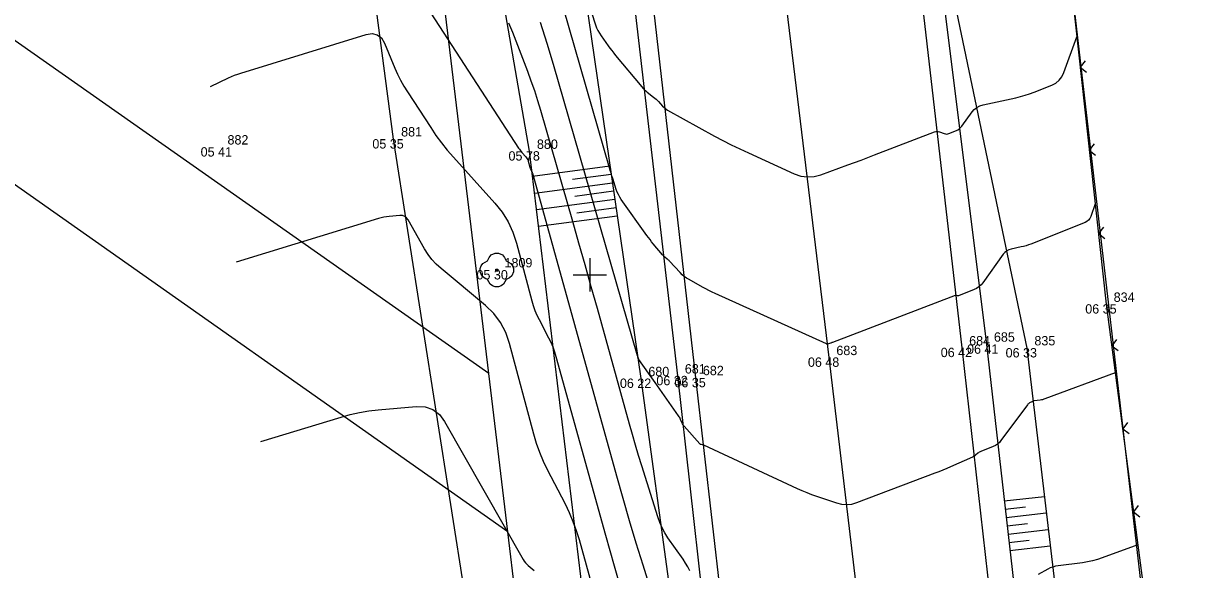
# Model space of a CAD drawing. Extents: x -711234 to -710007, y -1026313 to -1025448.
# Drawn here: x -710916.93 to -710881.89, y -1026008.8 to -1025992.49 of the extents above; entities that cross this region are included whole.
import ezdxf

# ---------------------------------------------------------------- set-up
doc = ezdxf.new("R2010")
doc.units = 0
for name, color, linetype in [('Ex_Major Contours', 7, 'Continuous'), ('Ex_Minor Contours', 7, 'Continuous'), ('Z_body', 7, 'Continuous'), ('Z_body_cisla', 7, 'Continuous'), ('Z_body_vysky_redukovane', 7, 'Continuous'), ('Z_hektometricka_sit', 7, 'Continuous'), ('Z_hrany_paty', 7, 'Continuous'), ('Z_katastr_hranice', 7, 'Continuous'), ('Z_komunikace', 7, 'Continuous'), ('Z_komunikace_osa', 7, 'Continuous'), ('Z_ploty', 7, 'Continuous'), ('Z_ploty_znacky', 7, 'Continuous'), ('Z_pole_rozhranni', 7, 'Continuous'), ('Z_technicke_srafy', 7, 'Continuous'), ('Z_vdz12_plna', 7, 'Continuous'), ('Z_zelen_jednotliva', 7, 'Continuous')]:
    doc.layers.add(name, color=color, linetype=linetype)

# ---------------------------------------------------------------- blocks, each defined once
blk = doc.blocks.new('POINT_DISPLAY')
blk.add_line((0, 0), (0, 0))
blk = doc.blocks.new('Z24')
for p, q in [((-0.28, 0.28), (-0.23, 0.38)), ((-0.23, 0.38), (-0.17, 0.45)), ((-0.17, 0.45), (-0.05, 0.5)), ((-0.05, 0.5), (0.05, 0.5)), ((0.05, 0.5), (0.17, 0.45)), ((0.17, 0.45), (0.23, 0.38)), ((0.23, 0.38), (0.28, 0.28)), ((-0.5, 0.05), (-0.47, 0.13)), ((-0.5, -0.05), (-0.5, 0.05)), ((-0.47, 0.13), (-0.42, 0.2)), ((-0.42, 0.2), (-0.28, 0.28)), ((-0.03, -0.03), (-0.03, 0.03)), ((-0.03, 0.03), (0.03, 0.03)), ((0.03, 0.03), (0.03, -0.03)), ((0.28, 0.28), (0.42, 0.2)), ((0.42, 0.2), (0.47, 0.13)), ((0.47, 0.13), (0.5, 0.05)), ((0.5, 0.05), (0.5, -0.05)), ((-0.45, -0.17), (-0.5, -0.05)), ((-0.38, -0.23), (-0.45, -0.17)), ((-0.28, -0.28), (-0.38, -0.23)), ((-0.2, -0.42), (-0.28, -0.28)), ((0.03, -0.03), (-0.03, -0.03)), ((0.28, -0.28), (0.2, -0.42)), ((0.38, -0.23), (0.28, -0.28)), ((0.45, -0.17), (0.38, -0.23)), ((0.5, -0.05), (0.45, -0.17)), ((-0.13, -0.47), (-0.2, -0.42)), ((-0.05, -0.5), (-0.13, -0.47)), ((0.05, -0.5), (-0.05, -0.5)), ((0.13, -0.47), (0.05, -0.5)), ((0.2, -0.42), (0.13, -0.47))]:
    blk.add_line(p, q)
blk = doc.blocks.new('Z212')
for p, q in [((-0.17, 0.17), (0, 0)), ((0, 0), (0.17, 0.17))]:
    blk.add_line(p, q)

msp = doc.modelspace()

# ---------------------------------------------------------------- linework, layer by layer
at = {"layer": 'Ex_Major Contours'}
for points in [[(-710897.009, -1026008.843), (-710897.072, -1026008.725), (-710897.14, -1026008.61), (-710897.214, -1026008.499), (-710897.664, -1026007.856), (-710897.758, -1026007.709), (-710897.841, -1026007.556), (-710897.911, -1026007.397), (-710897.97, -1026007.233), (-710898.446, -1026005.707), (-710898.541, -1026005.396), (-710898.635, -1026005.085), (-710898.725, -1026004.773), (-710898.813, -1026004.46), (-710899.773, -1026001.009), (-710899.955, -1026000.357), (-710900.138, -1025999.706), (-710900.323, -1025999.055), (-710900.51, -1025998.405), (-710901.463, -1025995.099), (-710901.552, -1025994.803), (-710901.647, -1025994.508), (-710901.749, -1025994.216), (-710901.856, -1025993.926), (-710902.299, -1025992.769), (-710902.417, -1025992.484)], [(-710909.834, -1026004.985), (-710907.436, -1026004.253), (-710907.162, -1026004.177), (-710906.885, -1026004.116), (-710906.606, -1026004.069), (-710906.324, -1026004.037), (-710905.188, -1026003.939), (-710904.922, -1026003.949), (-710904.692, -1026004.026), (-710904.497, -1026004.172), (-710904.339, -1026004.385), (-710901.991, -1026008.509), (-710901.96, -1026008.559), (-710901.924, -1026008.605), (-710901.885, -1026008.647), (-710901.842, -1026008.686), (-710901.662, -1026008.836)], [(-710883.621, -1026008.064), (-710884.686, -1026008.458), (-710884.828, -1026008.506), (-710884.973, -1026008.546), (-710885.12, -1026008.577), (-710885.268, -1026008.6), (-710886.003, -1026008.693), (-710886.083, -1026008.707), (-710886.161, -1026008.729), (-710886.236, -1026008.758), (-710886.308, -1026008.795), (-710886.594, -1026008.957)]]:
    msp.add_lwpolyline(points, dxfattribs=at)
at = {"layer": 'Ex_Minor Contours'}
for points in [[(-710884.89, -1025997.884), (-710885.027, -1025998.261), (-710885.055, -1025998.319), (-710885.092, -1025998.367), (-710885.139, -1025998.406), (-710885.197, -1025998.436), (-710886.817, -1025999.083), (-710886.888, -1025999.11), (-710886.96, -1025999.133), (-710887.033, -1025999.154), (-710887.107, -1025999.171), (-710887.403, -1025999.235), (-710887.474, -1025999.257), (-710887.537, -1025999.29), (-710887.592, -1025999.334), (-710887.64, -1025999.39), (-710888.252, -1026000.239), (-710888.306, -1026000.304), (-710888.368, -1026000.36), (-710888.436, -1026000.406), (-710888.512, -1026000.443), (-710888.974, -1026000.629), (-710888.982, -1026000.632), (-710888.991, -1026000.633), (-710888.999, -1026000.632), (-710889.008, -1026000.63), (-710889.043, -1026000.617), (-710889.051, -1026000.615), (-710889.06, -1026000.614), (-710889.069, -1026000.615), (-710889.077, -1026000.618), (-710892.749, -1026002.022), (-710892.764, -1026002.028), (-710892.779, -1026002.033), (-710892.794, -1026002.039), (-710892.809, -1026002.044), (-710892.868, -1026002.066), (-710892.883, -1026002.07), (-710892.898, -1026002.071), (-710892.912, -1026002.069), (-710892.927, -1026002.064), (-710896.248, -1026000.561), (-710896.344, -1026000.516), (-710896.439, -1026000.47), (-710896.534, -1026000.421), (-710896.627, -1026000.371), (-710897.034, -1026000.146), (-710897.107, -1026000.102), (-710897.175, -1026000.053), (-710897.239, -1025999.998), (-710897.299, -1025999.937), (-710897.614, -1025999.594), (-710897.631, -1025999.577), (-710897.648, -1025999.561), (-710897.666, -1025999.545), (-710897.684, -1025999.53), (-710897.759, -1025999.471), (-710897.777, -1025999.456), (-710897.795, -1025999.44), (-710897.812, -1025999.423), (-710897.827, -1025999.406), (-710898.101, -1025999.076), (-710898.151, -1025999.015), (-710898.2, -1025998.952), (-710898.248, -1025998.889), (-710898.295, -1025998.825), (-710899.059, -1025997.749), (-710899.105, -1025997.679), (-710899.145, -1025997.606), (-710899.18, -1025997.53), (-710899.209, -1025997.451), (-710899.313, -1025997.13), (-710899.339, -1025997.05), (-710899.364, -1025996.969), (-710899.388, -1025996.888), (-710899.412, -1025996.807), (-710900.786, -1025992.042)], [(-710900.066, -1025991.799), (-710899.826, -1025992.536), (-710899.795, -1025992.622), (-710899.757, -1025992.704), (-710899.714, -1025992.784), (-710899.664, -1025992.86), (-710899.452, -1025993.158), (-710899.398, -1025993.232), (-710899.343, -1025993.305), (-710899.286, -1025993.377), (-710899.229, -1025993.448), (-710898.448, -1025994.386), (-710898.411, -1025994.428), (-710898.371, -1025994.469), (-710898.33, -1025994.507), (-710898.286, -1025994.543), (-710898.092, -1025994.694), (-710898.055, -1025994.724), (-710898.019, -1025994.755), (-710897.985, -1025994.789), (-710897.951, -1025994.823), (-710897.822, -1025994.965), (-710897.788, -1025994.999), (-710897.752, -1025995.029), (-710897.713, -1025995.057), (-710897.673, -1025995.082), (-710896.272, -1025995.856), (-710896.023, -1025995.99), (-710895.771, -1025996.119), (-710895.518, -1025996.243), (-710895.261, -1025996.363), (-710893.889, -1025996.983), (-710893.693, -1025997.052), (-710893.496, -1025997.079), (-710893.297, -1025997.067), (-710893.096, -1025997.014), (-710892.291, -1025996.721), (-710892.09, -1025996.648), (-710891.889, -1025996.573), (-710891.689, -1025996.498), (-710891.489, -1025996.422), (-710889.693, -1025995.735), (-710889.658, -1025995.725), (-710889.622, -1025995.722), (-710889.587, -1025995.724), (-710889.551, -1025995.734), (-710889.408, -1025995.785), (-710889.372, -1025995.794), (-710889.337, -1025995.797), (-710889.301, -1025995.793), (-710889.266, -1025995.782), (-710889.042, -1025995.692), (-710888.995, -1025995.669), (-710888.953, -1025995.641), (-710888.915, -1025995.606), (-710888.882, -1025995.566), (-710888.574, -1025995.139), (-710888.507, -1025995.061), (-710888.43, -1025995), (-710888.343, -1025994.954), (-710888.245, -1025994.924), (-710887.264, -1025994.713), (-710887.126, -1025994.68), (-710886.989, -1025994.641), (-710886.854, -1025994.597), (-710886.721, -1025994.547), (-710886.191, -1025994.336), (-710886.069, -1025994.273), (-710885.969, -1025994.189), (-710885.889, -1025994.086), (-710885.83, -1025993.962), (-710885.441, -1025992.89)], [(-710904.75, -1025992.192), (-710902.129, -1025996.215), (-710902.106, -1025996.25), (-710902.081, -1025996.283), (-710902.055, -1025996.315), (-710902.028, -1025996.347), (-710901.911, -1025996.477), (-710901.888, -1025996.505), (-710901.869, -1025996.536), (-710901.854, -1025996.569), (-710901.842, -1025996.604), (-710901.793, -1025996.789), (-710901.788, -1025996.804), (-710901.783, -1025996.819), (-710901.777, -1025996.834), (-710901.769, -1025996.849), (-710901.739, -1025996.907), (-710901.732, -1025996.921), (-710901.726, -1025996.936), (-710901.721, -1025996.952), (-710901.716, -1025996.967), (-710899.204, -1026006.006), (-710899.015, -1026006.674), (-710898.822, -1026007.341), (-710898.623, -1026008.006), (-710898.418, -1026008.669), (-710897.225, -1026012.492)], [(-710884.292, -1026002.933), (-710886.394, -1026003.71), (-710886.428, -1026003.721), (-710886.463, -1026003.731), (-710886.499, -1026003.738), (-710886.535, -1026003.744), (-710886.713, -1026003.767), (-710886.732, -1026003.77), (-710886.751, -1026003.775), (-710886.769, -1026003.782), (-710886.787, -1026003.791), (-710886.856, -1026003.83), (-710886.873, -1026003.841), (-710886.888, -1026003.853), (-710886.902, -1026003.867), (-710886.914, -1026003.882), (-710887.709, -1026004.953), (-710887.757, -1026005.009), (-710887.811, -1026005.057), (-710887.872, -1026005.098), (-710887.939, -1026005.13), (-710888.313, -1026005.279), (-710888.335, -1026005.289), (-710888.357, -1026005.301), (-710888.378, -1026005.314), (-710888.397, -1026005.329), (-710888.474, -1026005.392), (-710888.494, -1026005.407), (-710888.515, -1026005.421), (-710888.536, -1026005.433), (-710888.558, -1026005.444), (-710889.214, -1026005.734), (-710889.331, -1026005.785), (-710889.449, -1026005.834), (-710889.567, -1026005.882), (-710889.686, -1026005.928), (-710892.028, -1026006.816), (-710892.175, -1026006.858), (-710892.323, -1026006.874), (-710892.47, -1026006.863), (-710892.619, -1026006.826), (-710893.213, -1026006.625), (-710893.36, -1026006.572), (-710893.506, -1026006.516), (-710893.651, -1026006.456), (-710893.794, -1026006.392), (-710896.591, -1026005.092), (-710896.601, -1026005.088), (-710896.61, -1026005.084), (-710896.62, -1026005.082), (-710896.631, -1026005.08), (-710896.672, -1026005.073), (-710896.682, -1026005.071), (-710896.691, -1026005.067), (-710896.699, -1026005.061), (-710896.707, -1026005.054), (-710897.177, -1026004.526), (-710897.196, -1026004.503), (-710897.212, -1026004.479), (-710897.227, -1026004.454), (-710897.239, -1026004.428), (-710897.286, -1026004.32), (-710897.299, -1026004.294), (-710897.313, -1026004.268), (-710897.327, -1026004.243), (-710897.344, -1026004.218), (-710898.044, -1026003.218), (-710898.093, -1026003.147), (-710898.143, -1026003.076), (-710898.193, -1026003.006), (-710898.243, -1026002.935), (-710898.533, -1026002.527), (-710898.538, -1026002.519), (-710898.542, -1026002.511), (-710898.546, -1026002.503), (-710898.549, -1026002.495), (-710898.56, -1026002.46), (-710898.566, -1026002.443), (-710898.571, -1026002.426), (-710901.081, -1025993.723), (-710901.271, -1025993.09), (-710901.474, -1025992.461)], [(-710911.343, -1025994.376), (-710910.802, -1025994.121), (-710910.711, -1025994.08), (-710910.619, -1025994.042), (-710910.526, -1025994.008), (-710910.431, -1025993.977), (-710906.682, -1025992.827), (-710906.503, -1025992.798), (-710906.353, -1025992.831), (-710906.231, -1025992.926), (-710906.139, -1025993.082), (-710905.827, -1025993.828), (-710905.745, -1025994.013), (-710905.655, -1025994.193), (-710905.556, -1025994.369), (-710905.45, -1025994.541), (-710904.755, -1025995.607), (-710904.598, -1025995.838), (-710904.433, -1025996.062), (-710904.259, -1025996.28), (-710904.076, -1025996.491), (-710902.838, -1025997.864), (-710902.623, -1025998.132), (-710902.443, -1025998.42), (-710902.3, -1025998.727), (-710902.192, -1025999.053), (-710901.733, -1026000.776), (-710901.69, -1026000.922), (-710901.64, -1026001.064), (-710901.581, -1026001.204), (-710901.515, -1026001.34), (-710901.235, -1026001.88), (-710901.169, -1026002.016), (-710901.11, -1026002.156), (-710901.058, -1026002.298), (-710901.014, -1026002.443), (-710899.53, -1026007.782), (-710899.274, -1026008.69), (-710899.01, -1026009.597)], [(-710899.522, -1026010.761), (-710900.312, -1026007.919), (-710900.396, -1026007.644), (-710900.494, -1026007.375), (-710900.606, -1026007.111), (-710900.731, -1026006.853), (-710901.261, -1026005.831), (-710901.386, -1026005.573), (-710901.496, -1026005.309), (-710901.592, -1026005.039), (-710901.674, -1026004.764), (-710902.397, -1026002.049), (-710902.51, -1026001.723), (-710902.669, -1026001.426), (-710902.872, -1026001.158), (-710903.12, -1026000.918), (-710904.447, -1025999.816), (-710904.589, -1025999.686), (-710904.718, -1025999.545), (-710904.834, -1025999.393), (-710904.937, -1025999.23), (-710905.432, -1025998.36), (-710905.478, -1025998.299), (-710905.533, -1025998.257), (-710905.599, -1025998.235), (-710905.675, -1025998.233), (-710906, -1025998.261), (-710906.08, -1025998.27), (-710906.16, -1025998.283), (-710906.239, -1025998.301), (-710906.317, -1025998.322), (-710910.575, -1025999.622)]]:
    msp.add_lwpolyline(points, dxfattribs=at)
at = {"layer": 'Z_hektometricka_sit'}
for p, q in [((-710900, -1025999.5), (-710900, -1026000.5)), ((-710900.5, -1026000), (-710899.5, -1026000))]:
    msp.add_line(p, q, dxfattribs=at)
at = {"layer": 'Z_hrany_paty'}
for p, q in [((-710901.8, -1025996.31), (-710904.29, -1025982.08)), ((-710900.9, -1025986.46), (-710898.47, -1026003.1)), ((-710889.89, -1025988.09), (-710886.94, -1026002.19)), ((-710899.51, -1026015.29), (-710901.8, -1025996.31)), ((-710886.94, -1026002.19), (-710885.11, -1026017.61)), ((-710898.47, -1026003.1), (-710896.6, -1026016.91))]:
    msp.add_line(p, q, dxfattribs=at)
at = {"layer": 'Z_katastr_hranice'}
for p, q in [((-710902.45, -1026007.68), (-710961.26, -1025966.3)), ((-710902.45, -1026007.68), (-710903.02, -1026002.95)), ((-710896.69, -1026055.45), (-710902.45, -1026007.68))]:
    msp.add_line(p, q, dxfattribs=at)
for points in [[(-710903.02, -1026002.95), (-710907.6, -1025964.93), (-710910.15, -1025942.26)], [(-710903.02, -1026002.95), (-710959.27, -1025963.47), (-710961.26, -1025966.3)], [(-710869.22, -1026132.07), (-710876.56, -1026069.18), (-710887.07, -1025978.66), (-710888.56, -1025976.86)]]:
    msp.add_lwpolyline(points, dxfattribs=at)
at = {"layer": 'Z_komunikace'}
for p, q in [((-710889.89, -1025988.09), (-710888.14, -1026002.08)), ((-710899.07, -1025988.51), (-710897.38, -1026003.02)), ((-710888.14, -1026002.08), (-710886.52, -1026016.3)), ((-710897.38, -1026003.02), (-710895.81, -1026017.01))]:
    msp.add_line(p, q, dxfattribs=at)
at = {"layer": 'Z_komunikace_osa'}
for p, q in [((-710894.58, -1025988.31), (-710892.85, -1026002.47)), ((-710892.85, -1026002.47), (-710891.15, -1026016.81))]:
    msp.add_line(p, q, dxfattribs=at)
at = {"layer": 'Z_ploty'}
for p, q in [((-710886.3, -1025985.1), (-710884.56, -1026000.88)), ((-710884.56, -1026000.88), (-710882.52, -1026016.48))]:
    msp.add_line(p, q, dxfattribs=at)
at = {"layer": 'Z_pole_rozhranni'}
for p, q in [((-710905.87, -1025995.95), (-710907.91, -1025980.39)), ((-710902.8, -1026015.46), (-710905.87, -1025995.95))]:
    msp.add_line(p, q, dxfattribs=at)
at = {"layer": 'Z_technicke_srafy'}
for p, q in [((-710899.4, -1025996.76), (-710901.71, -1025997.07)), ((-710899.36, -1025997.01), (-710900.52, -1025997.16)), ((-710899.32, -1025997.26), (-710901.65, -1025997.57)), ((-710899.29, -1025997.5), (-710900.45, -1025997.66)), ((-710899.25, -1025997.75), (-710901.59, -1025998.06)), ((-710899.21, -1025998), (-710900.39, -1025998.16)), ((-710899.18, -1025998.25), (-710901.53, -1025998.56)), ((-710887.61, -1026006.75), (-710886.41, -1026006.62)), ((-710887.58, -1026007), (-710886.98, -1026006.93)), ((-710887.55, -1026007.25), (-710886.36, -1026007.11)), ((-710887.52, -1026007.5), (-710886.92, -1026007.43)), ((-710887.49, -1026007.75), (-710886.3, -1026007.61)), ((-710887.47, -1026008), (-710886.87, -1026007.93)), ((-710887.44, -1026008.24), (-710886.24, -1026008.1))]:
    msp.add_line(p, q, dxfattribs=at)
at = {"layer": 'Z_vdz12_plna'}
for p, q in [((-710890.5, -1025988.06), (-710888.88, -1026002.18)), ((-710898.49, -1025988.6), (-710896.84, -1026003.08)), ((-710888.88, -1026002.18), (-710887.26, -1026016.49)), ((-710896.84, -1026003.08), (-710895.23, -1026017.1))]:
    msp.add_line(p, q, dxfattribs=at)

# ---------------------------------------------------------------- block references
at = {"layer": 'Z_body'}
for p in [(-710905.87, -1025995.95), (-710911.05, -1025996.19), (-710901.8, -1025996.31), (-710902.78, -1025999.86), (-710884.56, -1026000.88), (-710888.88, -1026002.18), (-710888.14, -1026002.08), (-710886.94, -1026002.19), (-710892.85, -1026002.47), (-710898.47, -1026003.1), (-710897.38, -1026003.02), (-710896.84, -1026003.08)]:
    msp.add_blockref('POINT_DISPLAY', p, dxfattribs=at)
at = {"layer": 'Z_ploty_znacky'}
for p, rotation in [((-710885.34, -1025993.8), -83.7), ((-710885.07, -1025996.28), -83.7), ((-710884.79, -1025998.77), -83.7), ((-710884.4, -1026002.12), -82.50000000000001), ((-710884.07, -1026004.6), -82.50000000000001), ((-710883.75, -1026007.08), -82.50000000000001)]:
    msp.add_blockref('Z212', p, dxfattribs=dict(at, rotation=rotation))
at = {"layer": 'Z_zelen_jednotliva'}
msp.add_blockref('Z24', (-710902.78, -1025999.86), dxfattribs=at)

# ---------------------------------------------------------------- texts
at = {"layer": 'Z_body_cisla'}
for s, p in [('881', (-710905.64, -1025995.87)), ('882', (-710910.83, -1025996.11)), ('880', (-710901.58, -1025996.24)), ('1809', (-710902.55, -1025999.78)), ('834', (-710884.34, -1026000.81)), ('684', (-710888.66, -1026002.11)), ('685', (-710887.92, -1026002)), ('835', (-710886.71, -1026002.11)), ('683', (-710892.63, -1026002.4)), ('680', (-710898.25, -1026003.03)), ('681', (-710897.16, -1026002.95)), ('682', (-710896.62, -1026003))]:
    msp.add_text(s, height=0.28, dxfattribs=at).set_placement(p)
at = {"layer": 'Z_body_vysky_redukovane'}
for s, p in [('05 35', (-710906.5, -1025996.23)), ('05 41', (-710911.633, -1025996.47)), ('05 78', (-710902.43, -1025996.59)), ('05 30', (-710903.387, -1026000.14)), ('06 35', (-710885.19, -1026001.16)), ('06 42', (-710889.51, -1026002.46)), ('06 41', (-710888.723, -1026002.36)), ('06 33', (-710887.57, -1026002.47)), ('06 48', (-710893.48, -1026002.75)), ('06 22', (-710899.1, -1026003.38)), ('06 32', (-710898.01, -1026003.3)), ('06 35', (-710897.47, -1026003.36))]:
    msp.add_text(s, height=0.28, dxfattribs=at).set_placement(p)

doc.saveas('drawing.dxf')
